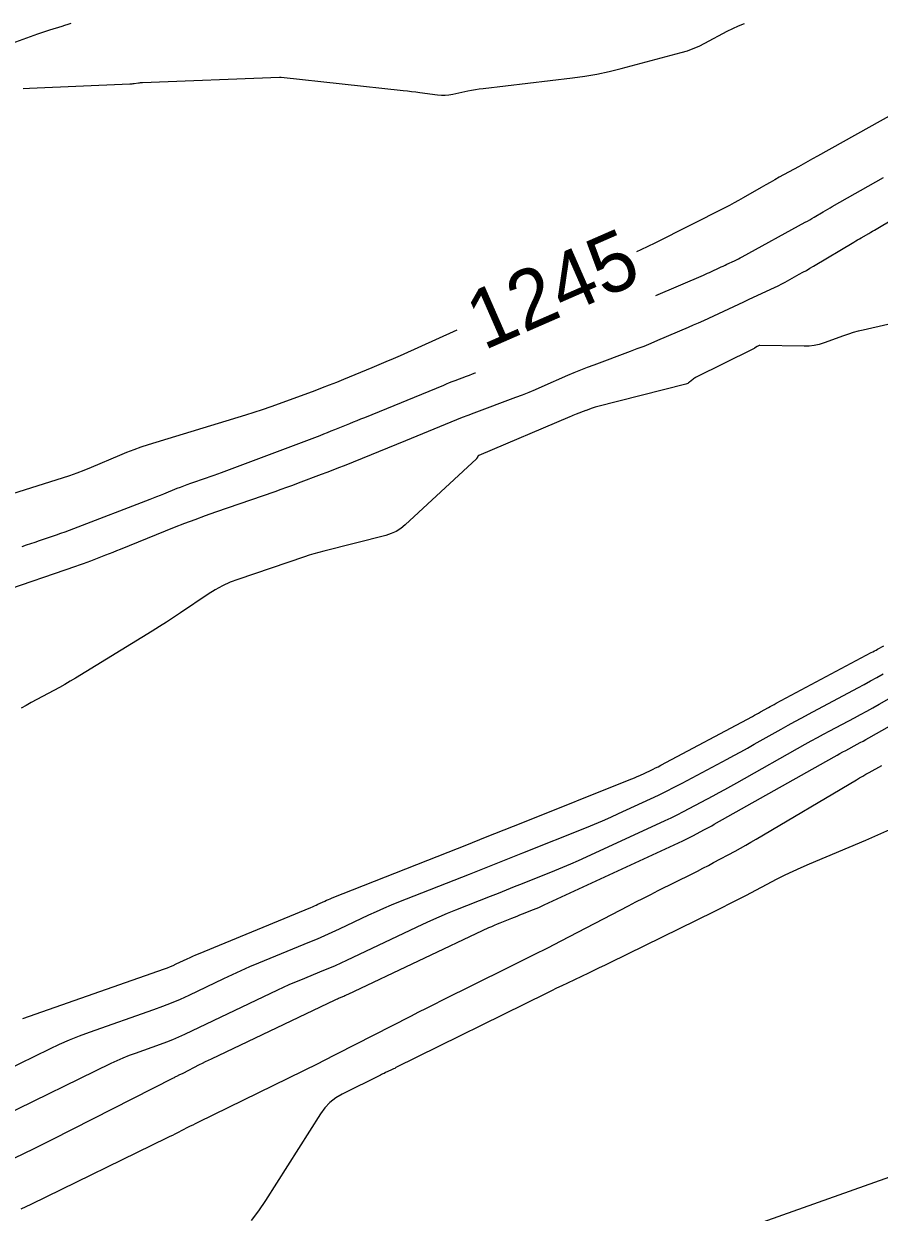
# Model space of a CAD drawing. Extents: x 658976 to 668721, y 639543 to 647196.
# Drawn here: x 662592.9 to 662680.1, y 642051.6 to 642172.8 of the extents above; entities that cross this region are included whole.
import ezdxf

# ---------------------------------------------------------------- set-up
doc = ezdxf.new("R2010")
doc.units = 0
for name, color, linetype in [('Ex_Contour Labels', 7, 'Continuous'), ('Ex_Major Contours', 7, 'Continuous'), ('Ex_Minor Contours', 7, 'Continuous')]:
    doc.layers.add(name, color=color, linetype=linetype)

msp = doc.modelspace()

# ---------------------------------------------------------------- linework, layer by layer
at = {"layer": 'Ex_Major Contours'}
for points in [[(662592.79, 642166.21), (662593.43, 642166.25), (662603.69, 642166.68), (662603.8, 642166.68), (662603.91, 642166.69), (662604.02, 642166.7), (662604.12, 642166.71), (662604.55, 642166.77), (662604.66, 642166.79), (662604.77, 642166.8), (662604.87, 642166.81), (662604.98, 642166.81), (662618.93, 642167.37), (662619, 642167.37), (662619.1, 642167.37), (662619.1, 642167.37), (662619.12, 642167.37), (662631.56, 642166), (662631.99, 642165.95), (662632.42, 642165.9), (662632.84, 642165.85), (662633.27, 642165.8), (662635.06, 642165.57), (662635.45, 642165.54), (662635.84, 642165.54), (662636.22, 642165.57), (662636.61, 642165.64), (662638.16, 642165.96), (662638.54, 642166.04), (662638.93, 642166.11), (662639.32, 642166.17), (662639.71, 642166.22), (662648.82, 642167.29), (662650.07, 642167.46), (662651.32, 642167.68), (662652.57, 642167.94), (662653.8, 642168.24), (662659.92, 642169.87), (662660.54, 642170.05), (662661.14, 642170.27), (662661.74, 642170.53), (662662.31, 642170.82), (662664.6, 642172.04), (662665.18, 642172.34), (662665.76, 642172.61), (662666.36, 642172.85)], [(662684.3, 642165.16), (662673.81, 642159.29), (662673.32, 642159.02), (662672.84, 642158.75), (662672.36, 642158.49), (662671.88, 642158.22), (662669.91, 642157.14), (662669.45, 642156.88), (662668.99, 642156.62), (662668.53, 642156.36), (662668.07, 642156.1), (662666.23, 642155.05), (662665.77, 642154.79), (662665.31, 642154.53), (662664.84, 642154.28), (662664.37, 642154.04), (662657.23, 642150.44), (662656.51, 642150.09), (662655.79, 642149.75), (662655.36, 642149.55)], [(662637.04, 642141.53), (662631.24, 642138.94), (662630.52, 642138.62), (662629.8, 642138.31), (662629.09, 642138.01), (662628.36, 642137.71), (662625.47, 642136.51), (662624.75, 642136.22), (662624.02, 642135.93), (662623.29, 642135.65), (662622.56, 642135.37), (662618.9, 642134.02), (662618.05, 642133.71), (662617.19, 642133.41), (662616.32, 642133.13), (662615.46, 642132.86), (662605.56, 642129.84), (662604.81, 642129.6), (662604.07, 642129.34), (662603.34, 642129.06), (662602.61, 642128.77), (662599.72, 642127.53), (662598.99, 642127.23), (662598.26, 642126.95), (662597.52, 642126.69), (662596.77, 642126.45), (662589.09, 642124.04)], [(662590.92, 642065.98), (662595.53, 642068.23), (662596.52, 642068.69), (662597.53, 642069.13), (662598.55, 642069.54), (662599.58, 642069.92), (662606.11, 642072.22), (662607.03, 642072.56), (662607.94, 642072.92), (662608.83, 642073.3), (662609.72, 642073.71), (662613.25, 642075.4), (662614.14, 642075.81), (662615.03, 642076.21), (662615.93, 642076.61), (662616.83, 642076.98), (662622.04, 642079.13), (662622.81, 642079.45), (662623.57, 642079.78), (662624.32, 642080.12), (662625.07, 642080.47), (662628.07, 642081.89), (662628.83, 642082.24), (662629.59, 642082.57), (662630.35, 642082.9), (662631.12, 642083.21), (662638.31, 642086.05), (662639.67, 642086.59), (662641.03, 642087.13), (662642.39, 642087.67), (662643.75, 642088.21), (662650.24, 642090.8), (662651.07, 642091.14), (662651.89, 642091.49), (662652.72, 642091.85), (662653.53, 642092.22), (662656.79, 642093.73), (662657.6, 642094.11), (662658.4, 642094.5), (662659.2, 642094.91), (662660, 642095.32), (662664.59, 642097.78), (662665.29, 642098.15), (662665.98, 642098.53), (662666.68, 642098.91), (662667.37, 642099.3), (662670.12, 642100.85), (662670.81, 642101.24), (662671.5, 642101.62), (662672.2, 642102), (662672.89, 642102.37), (662677.93, 642105.06), (662678.58, 642105.4), (662679.23, 642105.76), (662679.88, 642106.11), (662680.52, 642106.47)]]:
    msp.add_lwpolyline(points, dxfattribs=at)
at = {"layer": 'Ex_Minor Contours'}
for points in [[(662597.65, 642172.82), (662597.34, 642172.72), (662597.03, 642172.63), (662596.73, 642172.53), (662595.49, 642172.15), (662595.19, 642172.05), (662594.88, 642171.95), (662594.57, 642171.85), (662594.27, 642171.74), (662586.38, 642168.88)], [(662590.43, 642114.83), (662598.18, 642117.47), (662598.56, 642117.6), (662598.94, 642117.74), (662599.33, 642117.88), (662599.7, 642118.02), (662601.22, 642118.61), (662601.6, 642118.75), (662601.98, 642118.9), (662602.35, 642119.05), (662602.73, 642119.2), (662608.24, 642121.43), (662609.29, 642121.84), (662610.34, 642122.24), (662611.4, 642122.63), (662612.46, 642123.01), (662618.51, 642125.1), (662619.11, 642125.31), (662619.7, 642125.52), (662620.29, 642125.74), (662620.87, 642125.96), (662623.22, 642126.84), (662623.81, 642127.06), (662624.4, 642127.29), (662624.98, 642127.52), (662625.56, 642127.75), (662631.84, 642130.3), (662632.41, 642130.53), (662632.99, 642130.77), (662633.57, 642131.01), (662634.15, 642131.24), (662636.46, 642132.19), (662637.04, 642132.43), (662637.62, 642132.66), (662638.2, 642132.88), (662638.78, 642133.11), (662643.06, 642134.71), (662643.73, 642134.96), (662644.4, 642135.23), (662645.06, 642135.5), (662645.72, 642135.79), (662648.35, 642136.94), (662649.01, 642137.22), (662649.68, 642137.5), (662650.34, 642137.76), (662651.02, 642138.02), (662654.73, 642139.39), (662655.43, 642139.66), (662656.14, 642139.93), (662656.84, 642140.22), (662657.53, 642140.51), (662660.66, 642141.85), (662661.18, 642142.08), (662661.69, 642142.31), (662662.21, 642142.54), (662662.72, 642142.77), (662664.78, 642143.74), (662665.29, 642143.97), (662665.79, 642144.2), (662666.29, 642144.44), (662666.79, 642144.67), (662669.05, 642145.72), (662669.42, 642145.89), (662669.79, 642146.07), (662670.16, 642146.26), (662670.52, 642146.46), (662671.96, 642147.25), (662672.32, 642147.45), (662672.68, 642147.65), (662673.03, 642147.86), (662673.39, 642148.07), (662677.52, 642150.54), (662677.71, 642150.65), (662677.9, 642150.76), (662678.09, 642150.87), (662678.28, 642150.98), (662679.05, 642151.42), (662679.24, 642151.53), (662679.43, 642151.64), (662679.62, 642151.75), (662679.81, 642151.86), (662688.62, 642157.13)], [(662657.32, 642145.08), (662662.19, 642147.17), (662662.39, 642147.26), (662662.59, 642147.35), (662662.79, 642147.44), (662662.99, 642147.53), (662663.8, 642147.91), (662663.99, 642148), (662664.19, 642148.09), (662664.38, 642148.18), (662664.58, 642148.27), (662665.36, 642148.63), (662665.56, 642148.72), (662665.75, 642148.82), (662665.94, 642148.92), (662666.13, 642149.02), (662672.56, 642152.55), (662672.79, 642152.68), (662673.02, 642152.81), (662673.25, 642152.94), (662673.48, 642153.08), (662674.4, 642153.63), (662674.63, 642153.76), (662674.86, 642153.9), (662675.09, 642154.03), (662675.32, 642154.16), (662680.55, 642157.13)], [(662680.98, 642142.11), (662678.48, 642141.56), (662677.97, 642141.44), (662677.46, 642141.3), (662676.96, 642141.14), (662676.47, 642140.97), (662674.49, 642140.25), (662674, 642140.1), (662673.49, 642139.99), (662672.98, 642139.92), (662672.46, 642139.91), (662667.94, 642139.97), (662667.86, 642139.97), (662667.79, 642139.95), (662667.72, 642139.93), (662667.66, 642139.89), (662667.4, 642139.72), (662667.34, 642139.68), (662667.27, 642139.64), (662667.21, 642139.6), (662667.14, 642139.57), (662661.45, 642136.75), (662661.35, 642136.7), (662661.26, 642136.65), (662661.17, 642136.58), (662661.09, 642136.52), (662660.76, 642136.24), (662660.67, 642136.17), (662660.58, 642136.12), (662660.48, 642136.08), (662660.38, 642136.05), (662651.26, 642133.72), (662651.15, 642133.69), (662651.04, 642133.66), (662650.94, 642133.62), (662650.83, 642133.59), (662650.22, 642133.36), (662650.2, 642133.35), (662650.19, 642133.34), (662650.18, 642133.34), (662649.2, 642132.98), (662649.04, 642132.91), (662648.87, 642132.85), (662648.71, 642132.78), (662648.55, 642132.71), (662639.26, 642128.77), (662639.23, 642128.75), (662639.2, 642128.73), (662639.18, 642128.7), (662639.17, 642128.67), (662639.11, 642128.54), (662639.09, 642128.5), (662639.07, 642128.47), (662639.05, 642128.45), (662639.03, 642128.42), (662631.76, 642121.68), (662631.32, 642121.32), (662630.85, 642121.02), (662630.34, 642120.79), (662629.79, 642120.61), (662623.45, 642119), (662622.95, 642118.87), (662622.46, 642118.73), (662621.97, 642118.58), (662621.48, 642118.42), (662614.69, 642116.11), (662613.9, 642115.82), (662613.13, 642115.46), (662612.38, 642115.06), (662611.66, 642114.61), (662608.84, 642112.7), (662608.13, 642112.23), (662607.42, 642111.76), (662606.7, 642111.3), (662605.97, 642110.85), (662598.15, 642106.05), (662597.6, 642105.72), (662597.05, 642105.4), (662596.5, 642105.09), (662595.94, 642104.78), (662593.61, 642103.55), (662593.09, 642103.26), (662592.58, 642102.97)], [(662592.7, 642119.49), (662593.14, 642119.63), (662593.58, 642119.78), (662594.02, 642119.93), (662594.46, 642120.08), (662596.21, 642120.67), (662596.65, 642120.83), (662597.09, 642120.98), (662597.52, 642121.14), (662597.95, 642121.31), (662605.75, 642124.31), (662606.1, 642124.44), (662606.44, 642124.58), (662606.79, 642124.71), (662607.13, 642124.85), (662608.5, 642125.41), (662608.85, 642125.54), (662609.19, 642125.67), (662609.54, 642125.8), (662609.89, 642125.93), (662611.5, 642126.48), (662611.88, 642126.62), (662612.27, 642126.76), (662612.65, 642126.89), (662613.03, 642127.04), (662623.08, 642130.81), (662623.46, 642130.96), (662623.84, 642131.11), (662624.22, 642131.26), (662624.6, 642131.41), (662626.12, 642132.02), (662626.5, 642132.18), (662626.88, 642132.33), (662627.25, 642132.49), (662627.63, 642132.64), (662635.69, 642135.95), (662635.98, 642136.07), (662636.27, 642136.19), (662636.56, 642136.3), (662636.86, 642136.41), (662638.03, 642136.85), (662638.33, 642136.97), (662638.62, 642137.08), (662638.91, 642137.2), (662638.93, 642137.21)], [(662592.78, 642071.3), (662607.23, 642076.39), (662607.53, 642076.5), (662607.82, 642076.62), (662608.11, 642076.74), (662608.4, 642076.88), (662609.54, 642077.42), (662609.82, 642077.55), (662610.11, 642077.68), (662610.4, 642077.81), (662610.69, 642077.93), (662622.13, 642082.65), (662622.32, 642082.72), (662622.5, 642082.8), (662622.68, 642082.88), (662622.86, 642082.97), (662623.57, 642083.3), (662623.75, 642083.39), (662623.93, 642083.47), (662624.11, 642083.54), (662624.3, 642083.62), (662636.14, 642088.3), (662638.04, 642089.05), (662639.95, 642089.81), (662641.85, 642090.56), (662643.75, 642091.32), (662654.61, 642095.66), (662654.89, 642095.77), (662655.16, 642095.88), (662655.43, 642096), (662655.7, 642096.12), (662656.77, 642096.62), (662657.04, 642096.75), (662657.3, 642096.88), (662657.57, 642097.01), (662657.83, 642097.15), (662667.19, 642102.14), (662667.4, 642102.25), (662667.6, 642102.36), (662667.8, 642102.47), (662668, 642102.59), (662668.8, 642103.04), (662669, 642103.15), (662669.2, 642103.26), (662669.4, 642103.37), (662669.6, 642103.48), (662679.3, 642108.65), (662679.46, 642108.73), (662679.62, 642108.82), (662679.78, 642108.9), (662679.94, 642108.99), (662680.57, 642109.35)], [(662590.64, 642061.31), (662601.78, 642066.75), (662602.39, 642067.04), (662603.01, 642067.31), (662603.63, 642067.56), (662604.27, 642067.79), (662606.81, 642068.69), (662607.45, 642068.92), (662608.07, 642069.17), (662608.69, 642069.44), (662609.3, 642069.72), (662618.78, 642074.24), (662619.36, 642074.51), (662619.94, 642074.77), (662620.52, 642075.02), (662621.11, 642075.27), (662623.47, 642076.24), (662624.06, 642076.49), (662624.64, 642076.74), (662625.22, 642077.01), (662625.8, 642077.27), (662633.55, 642080.93), (662634.39, 642081.32), (662635.23, 642081.7), (662636.08, 642082.06), (662636.94, 642082.41), (662640.47, 642083.8), (662641.29, 642084.12), (662642.11, 642084.45), (662642.92, 642084.77), (662643.74, 642085.1), (662647.01, 642086.4), (662647.83, 642086.74), (662648.64, 642087.08), (662649.44, 642087.43), (662650.24, 642087.8), (662658.27, 642091.51), (662658.89, 642091.8), (662659.51, 642092.11), (662660.13, 642092.42), (662660.73, 642092.74), (662663.16, 642094.03), (662663.77, 642094.36), (662664.37, 642094.69), (662664.98, 642095.02), (662665.58, 642095.35), (662672.55, 642099.29), (662673.18, 642099.64), (662673.8, 642099.99), (662674.43, 642100.33), (662675.06, 642100.67), (662677.58, 642102.01), (662678.21, 642102.35), (662678.84, 642102.69), (662679.47, 642103.03), (662680.09, 642103.38), (662686.47, 642106.98)], [(662591.94, 642057.09), (662593.85, 642058.02), (662594.32, 642058.26), (662594.8, 642058.5), (662595.28, 642058.73), (662595.75, 642058.97), (662608.14, 642065.27), (662608.22, 642065.31), (662608.3, 642065.35), (662608.38, 642065.39), (662608.46, 642065.43), (662608.79, 642065.59), (662608.87, 642065.63), (662608.95, 642065.67), (662609.04, 642065.71), (662609.12, 642065.75), (662610.78, 642066.61), (662611.09, 642066.76), (662611.39, 642066.92), (662611.7, 642067.07), (662612.01, 642067.21), (662624.63, 642073.23), (662624.74, 642073.28), (662624.85, 642073.33), (662624.96, 642073.38), (662625.07, 642073.42), (662625.51, 642073.6), (662625.62, 642073.65), (662625.72, 642073.7), (662625.83, 642073.75), (662625.94, 642073.8), (662640.3, 642080.59), (662640.59, 642080.72), (662640.87, 642080.84), (662641.16, 642080.96), (662641.45, 642081.08), (662642.64, 642081.55), (662642.91, 642081.66), (662643.19, 642081.77), (662643.46, 642081.88), (662643.74, 642081.99), (662644.84, 642082.43), (662645.11, 642082.54), (662645.39, 642082.65), (662645.66, 642082.77), (662645.93, 642082.9), (662660.08, 642089.44), (662660.35, 642089.57), (662660.62, 642089.7), (662660.89, 642089.84), (662661.16, 642089.98), (662662.23, 642090.55), (662662.5, 642090.7), (662662.76, 642090.84), (662663.03, 642090.99), (662663.29, 642091.14), (662675.52, 642098.03), (662675.81, 642098.2), (662676.1, 642098.36), (662676.4, 642098.52), (662676.69, 642098.67), (662677.87, 642099.3), (662678.16, 642099.46), (662678.46, 642099.62), (662678.75, 642099.78), (662679.04, 642099.94), (662690.68, 642106.5)], [(662592.6, 642051.9), (662593.11, 642052.12), (662593.61, 642052.36), (662607.52, 642059.17), (662607.78, 642059.3), (662608.05, 642059.43), (662608.31, 642059.56), (662608.57, 642059.69), (662609.6, 642060.22), (662609.86, 642060.35), (662610.13, 642060.48), (662610.39, 642060.61), (662610.65, 642060.74), (662622.94, 642066.77), (662623.4, 642067), (662623.87, 642067.23), (662624.33, 642067.47), (662624.8, 642067.7), (662632.35, 642071.57), (662633.14, 642071.98), (662633.94, 642072.38), (662634.74, 642072.78), (662635.54, 642073.18), (662642.19, 642076.47), (662643.56, 642077.16), (662644.93, 642077.85), (662646.3, 642078.54), (662647.66, 642079.25), (662654.54, 642082.82), (662655.29, 642083.21), (662656.05, 642083.59), (662656.81, 642083.98), (662657.57, 642084.36), (662661.03, 642086.08), (662661.58, 642086.36), (662662.13, 642086.64), (662662.68, 642086.93), (662663.22, 642087.22), (662665.41, 642088.39), (662665.95, 642088.69), (662666.49, 642088.99), (662667.03, 642089.3), (662667.56, 642089.61), (662677.78, 642095.68), (662678.11, 642095.87), (662678.43, 642096.05), (662678.75, 642096.24), (662679.08, 642096.42), (662680.39, 642097.13)], [(662681.15, 642090.58), (662679.93, 642090.02), (662678.7, 642089.49), (662672.96, 642087.06), (662672.13, 642086.7), (662671.3, 642086.32), (662670.49, 642085.93), (662669.68, 642085.52), (662666.46, 642083.84), (662665.66, 642083.43), (662664.85, 642083.02), (662664.04, 642082.61), (662663.23, 642082.21), (662652.63, 642077), (662652.09, 642076.73), (662651.55, 642076.47), (662651.01, 642076.21), (662650.47, 642075.95), (662648.3, 642074.92), (662647.75, 642074.66), (662647.21, 642074.4), (662646.67, 642074.14), (662646.13, 642073.87), (662630.82, 642066.3), (662630.69, 642066.23), (662630.56, 642066.17), (662630.42, 642066.11), (662630.29, 642066.04), (662629.76, 642065.79), (662629.63, 642065.72), (662629.49, 642065.66), (662629.36, 642065.59), (662629.23, 642065.53), (662625.34, 642063.59), (662624.68, 642063.21), (662624.09, 642062.75), (662623.57, 642062.21), (662623.12, 642061.59), (662617.52, 642052.75), (662616.81, 642051.7), (662616.06, 642050.69)], [(662665.11, 642049.44), (662682.24, 642055.52)]]:
    msp.add_lwpolyline(points, dxfattribs=at)

# ---------------------------------------------------------------- texts
at = {"layer": 'Ex_Contour Labels'}
msp.add_text('1245', height=6, rotation=23.6398, dxfattribs=at).set_placement((662639.77, 642139.45))

doc.saveas('drawing.dxf')
